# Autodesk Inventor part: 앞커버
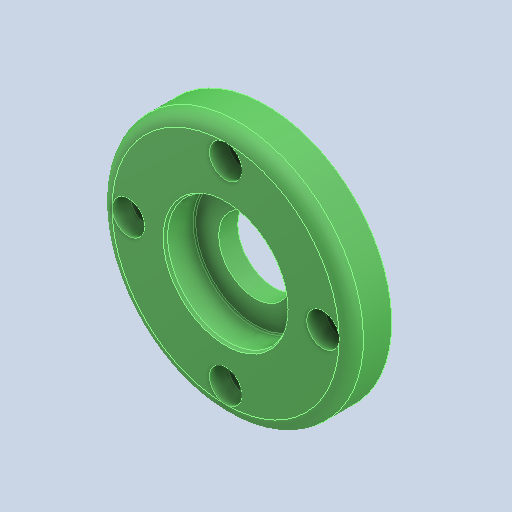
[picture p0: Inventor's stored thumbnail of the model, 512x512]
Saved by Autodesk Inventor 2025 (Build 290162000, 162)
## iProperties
Created: 2024-07
Part Number: 앞커버
Material: 알루미늄 6061
Document SubType Name: Modeling
Designer: onair
Density: 2.71 g/cm^3
Appearance: 기본값
Author: jhkim
Sending System: Autodesk Inventor 2025
Preprocessor: ST-DEVELOPER v20
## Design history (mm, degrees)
feature "솔리드1"
node "솔리드2"
